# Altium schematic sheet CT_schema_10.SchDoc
size 146 x 119 mm
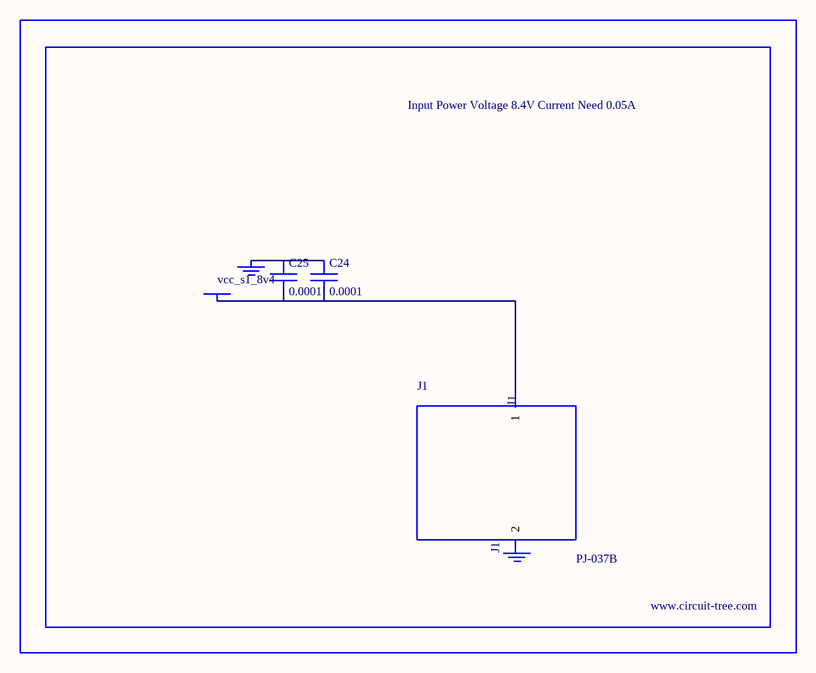
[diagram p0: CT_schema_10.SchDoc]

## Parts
BORDER9  (no value)
C24  0.0001  [EXV-9H]
C25  0.0001  [EXV-9H]
GND_INSTANCE_9_0  (no value)
GND_INSTANCE_9_1  (no value)
J1  PJ-037B  [PJ-037B_PACKAGE]
POWER_INSTANCE_9_0  vcc_s1_8v4

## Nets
NetC24_1: C24.1 C25.1 GND_INSTANCE_9_0.0(GND)
NetC24_2: C24.2 C25.2 J1.1 POWER_INSTANCE_9_0.0(PWR)

Not connected (* = marked no-connect by the designer): GND_INSTANCE_9_1 0(GND); J1 2

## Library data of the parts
BORDER9 = BORDER_PAGE9
C24 C25 = EDK107M035A9HAA
GND_INSTANCE_9_0 GND_INSTANCE_9_1 = GND
POWER_INSTANCE_9_0 = PWR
